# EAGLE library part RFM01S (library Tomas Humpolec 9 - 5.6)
RFM01 ISM BAND FSK RECEIVER MODULE General Introduction RFM01 is a low costing ISM band receiver module implemented with unique PLL and zero IF design approach. It works with FSK modulated signal ranges from 315/433/868/915MHZ bands, comply with FCC, ETSI regulation. The SPI interface is used to communicate with microcontroller for parameter setting. RFM01 works with RFM02 transmitter module. At 433MHZ band, the pair of module can work up to 300m in the free open air. Features: - Low costing, high performance and price ratio - Tuning free during production - FSK reception - PLL and zero IF technology - Fast PLL lock time - High resolution PLL with 2.5 KHz step - High data rate (up to 115.2 kbps with internal demodulator,with external RC filter highest data rate is 256 kbps) - Differential antenna input - Automatic antenna tuning - Programmable receiver bandwidth (from 67 to 400 kHz) - Analog and digital signal strength indicator (ARSSI/DRSSI) - AFC - DQD - Internal demodulator - SPI interface - Clock and reset signal output for external MCU use - 16 bits FIFO - Low power mode (Typical Application - Remote control - Remote sensor - Wireless data collection - Home security system - Toys - Tire pressure monitoring system http://www.TME.cz http://www.hoperf.com Tel: +86-755-82973806 E-mail: sales@hoperf.com
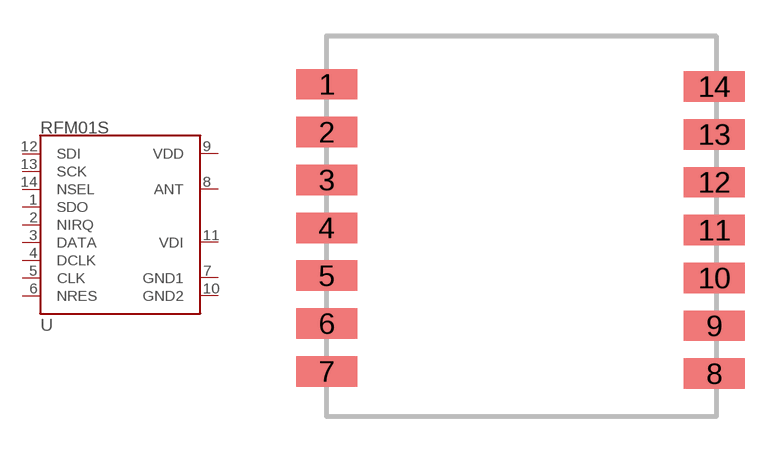
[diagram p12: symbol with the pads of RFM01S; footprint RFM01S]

Designator prefix -

## RFM01SSMD  [RFM01S]
1  SDO  out
2  NIRQ  out
3  DATA
4  DCLK
5  CLK  out
6  NRES
7  GND1  pwr
8  ANT  out
9  VDD  pwr
10  GND2  pwr
11  VDI  out
12  SDI  in
13  SCK  in
14  NSEL  in

## Footprint RFM01S (pad centres in mm)
smd 2.54 x 1.27: 1 0,13.905; 2 0,11.905; 3 0,9.905; 4 0,7.905; 5 0,5.905; 6 0,3.905; 7 0,1.905; 8 16.192,1.81; 9 16.192,3.81; 10 16.192,5.81; 11 16.192,7.81; 12 16.192,9.81; 13 16.192,11.81; 14 16.192,13.81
